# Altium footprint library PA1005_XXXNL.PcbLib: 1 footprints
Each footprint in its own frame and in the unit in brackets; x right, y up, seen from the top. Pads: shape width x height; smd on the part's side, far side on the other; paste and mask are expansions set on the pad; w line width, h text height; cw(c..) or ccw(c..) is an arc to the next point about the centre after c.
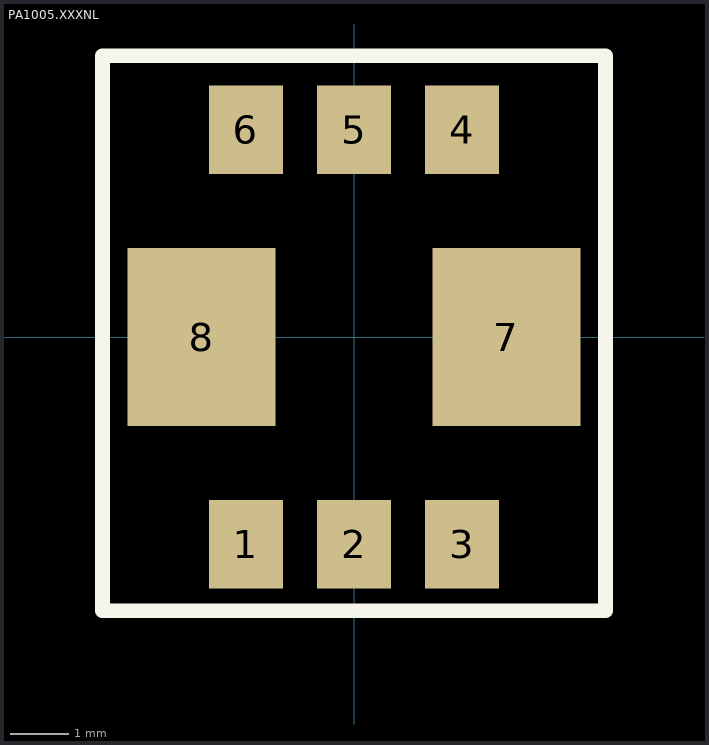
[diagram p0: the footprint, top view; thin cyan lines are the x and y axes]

## PA1005.XXXNL [mil] "PULSE ENGINEERING PA1005.XXXNL SERIES"
height 190
pads (9):
  round 30 on Top Overlay: 0(-145,-225)
  rect 50x60 smd: 1(-73,-140) 2(0,-140) 3(73,-140) 4(73,140) 5(0,140) 6(-73,140)
  rect 100x120 smd: 7(103,0) 8(-103,0)
Top Overlay:
  lines w10: -170,-185 -170,190 170,190 170,-185 -170,-185
M5 Assembly Top:
  text ".Designator" at -60,-20 h40
3D body: height 190, standoff 0, extent -170,-185 170,190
